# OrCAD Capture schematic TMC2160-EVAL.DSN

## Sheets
1 04_MOTOR-DRIVER: size Custom
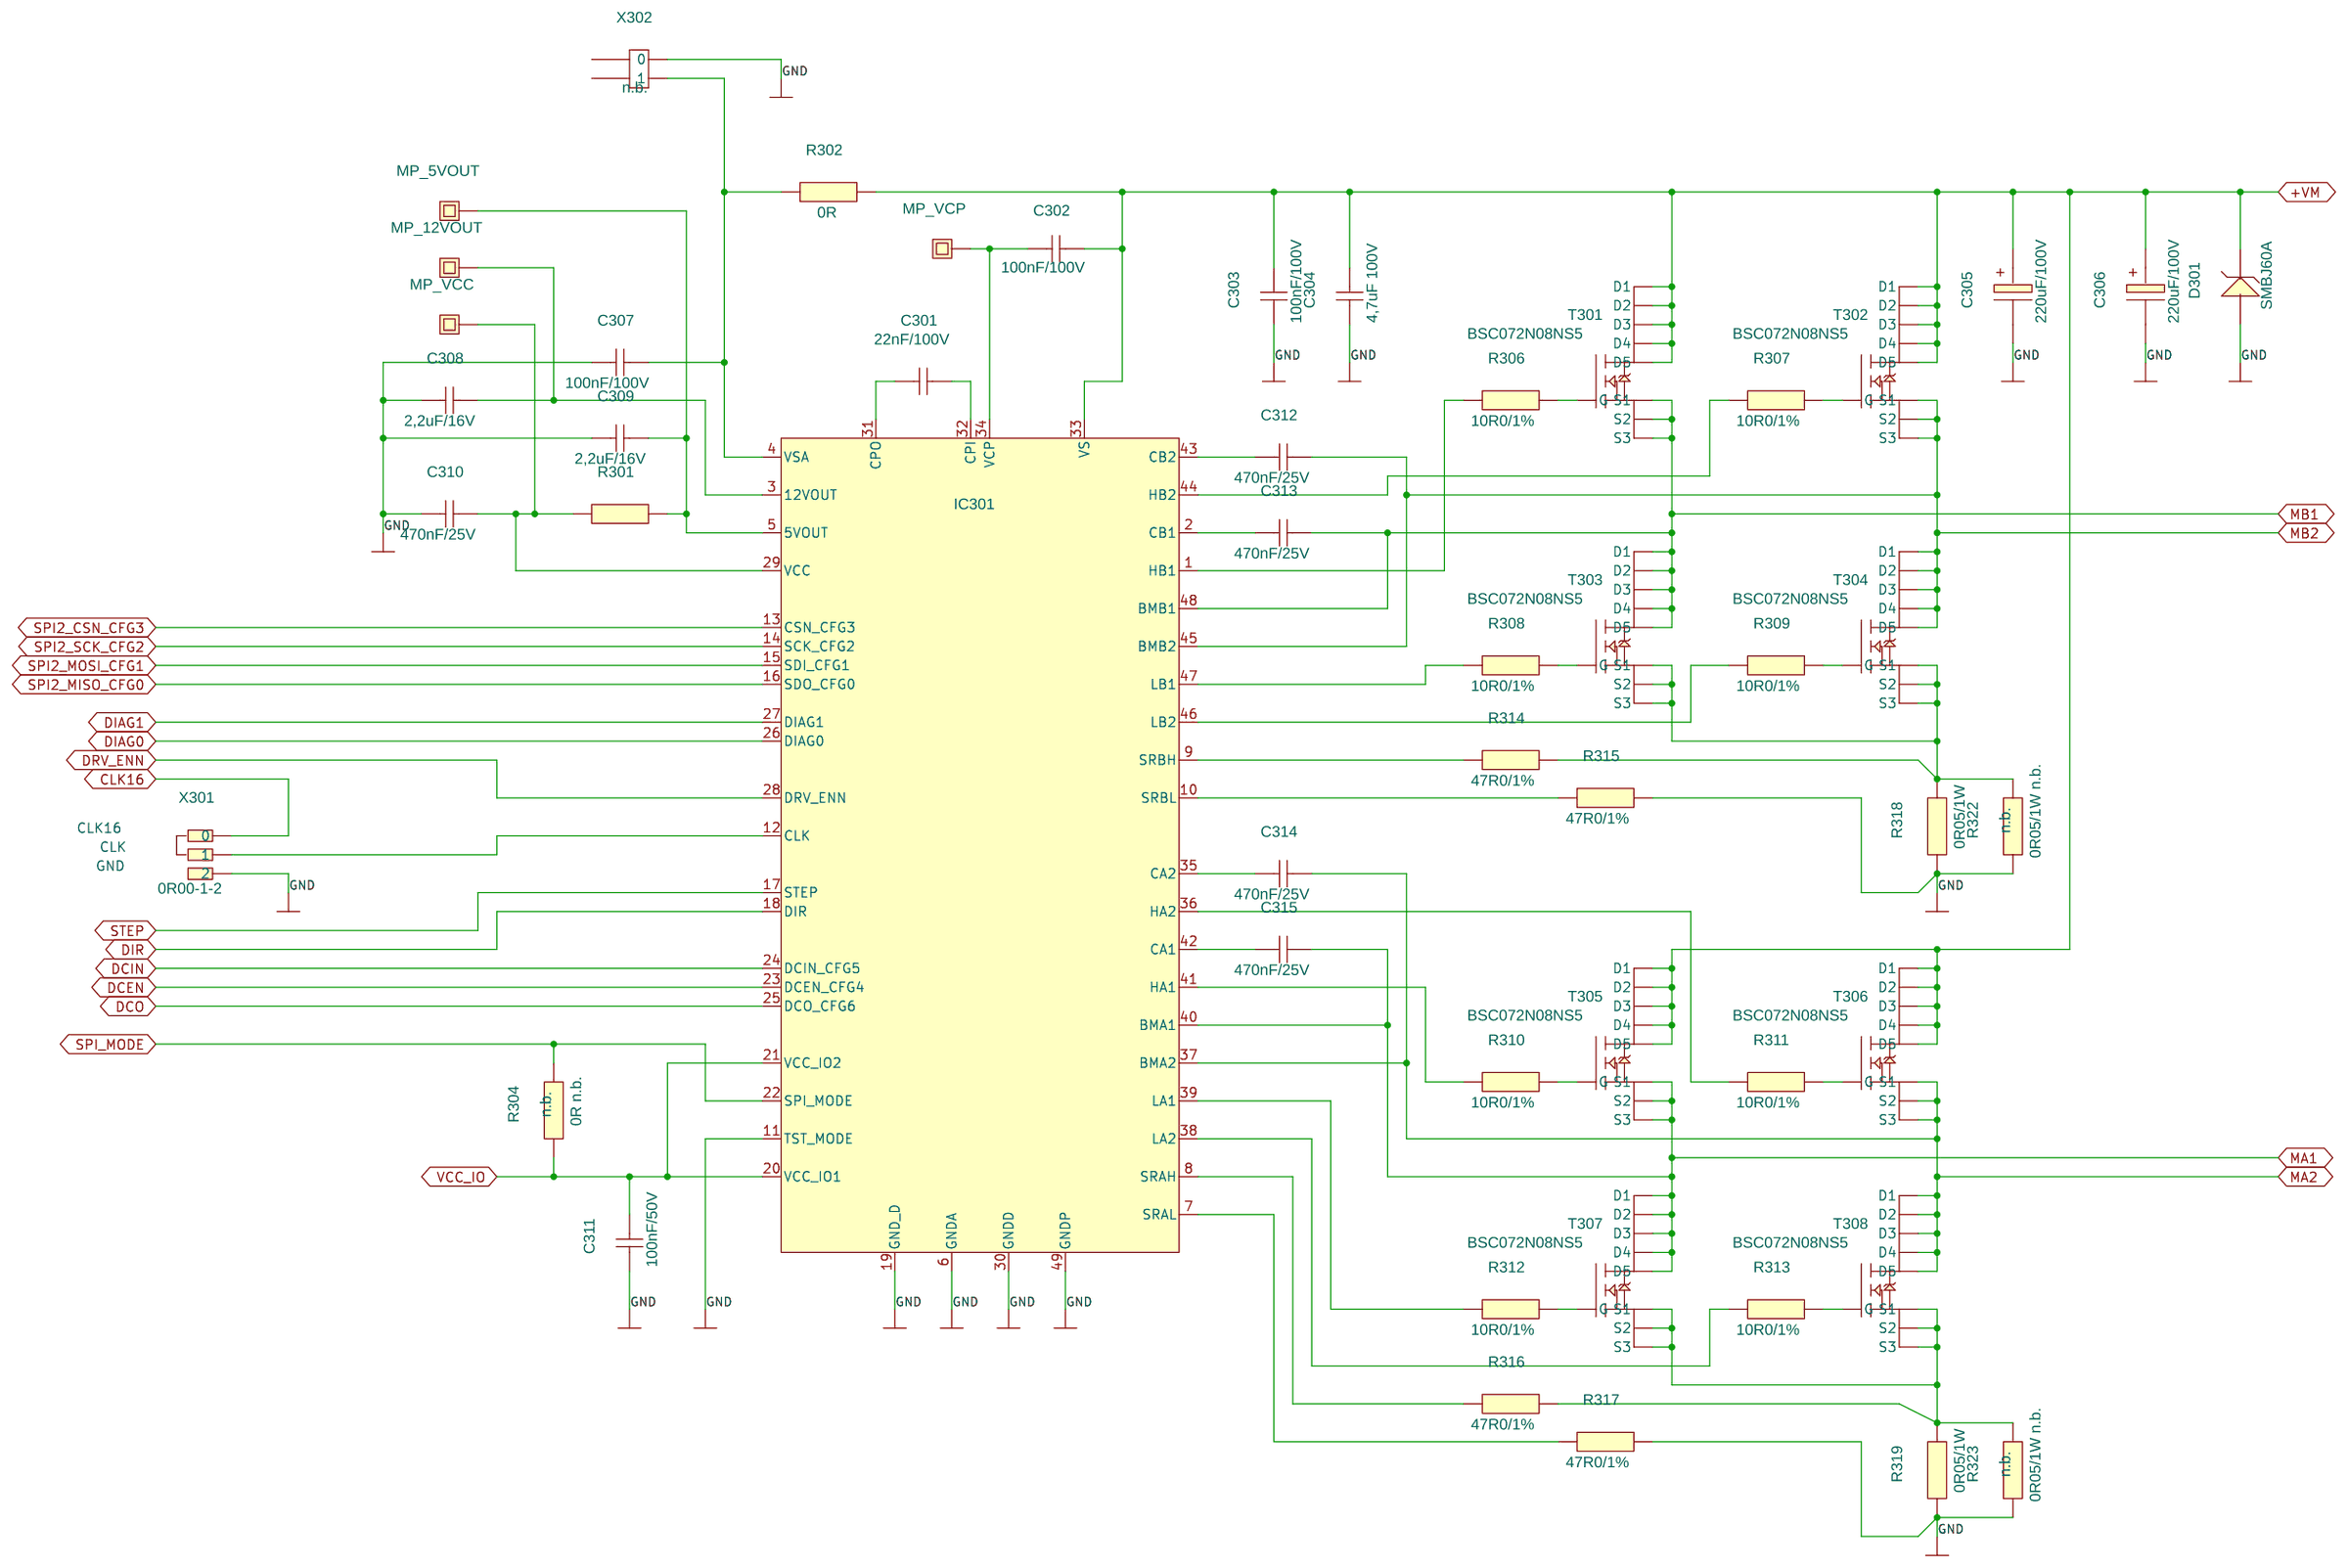
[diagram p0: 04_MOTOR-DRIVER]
2 03_MIXED-FUNCTIONS: size Custom
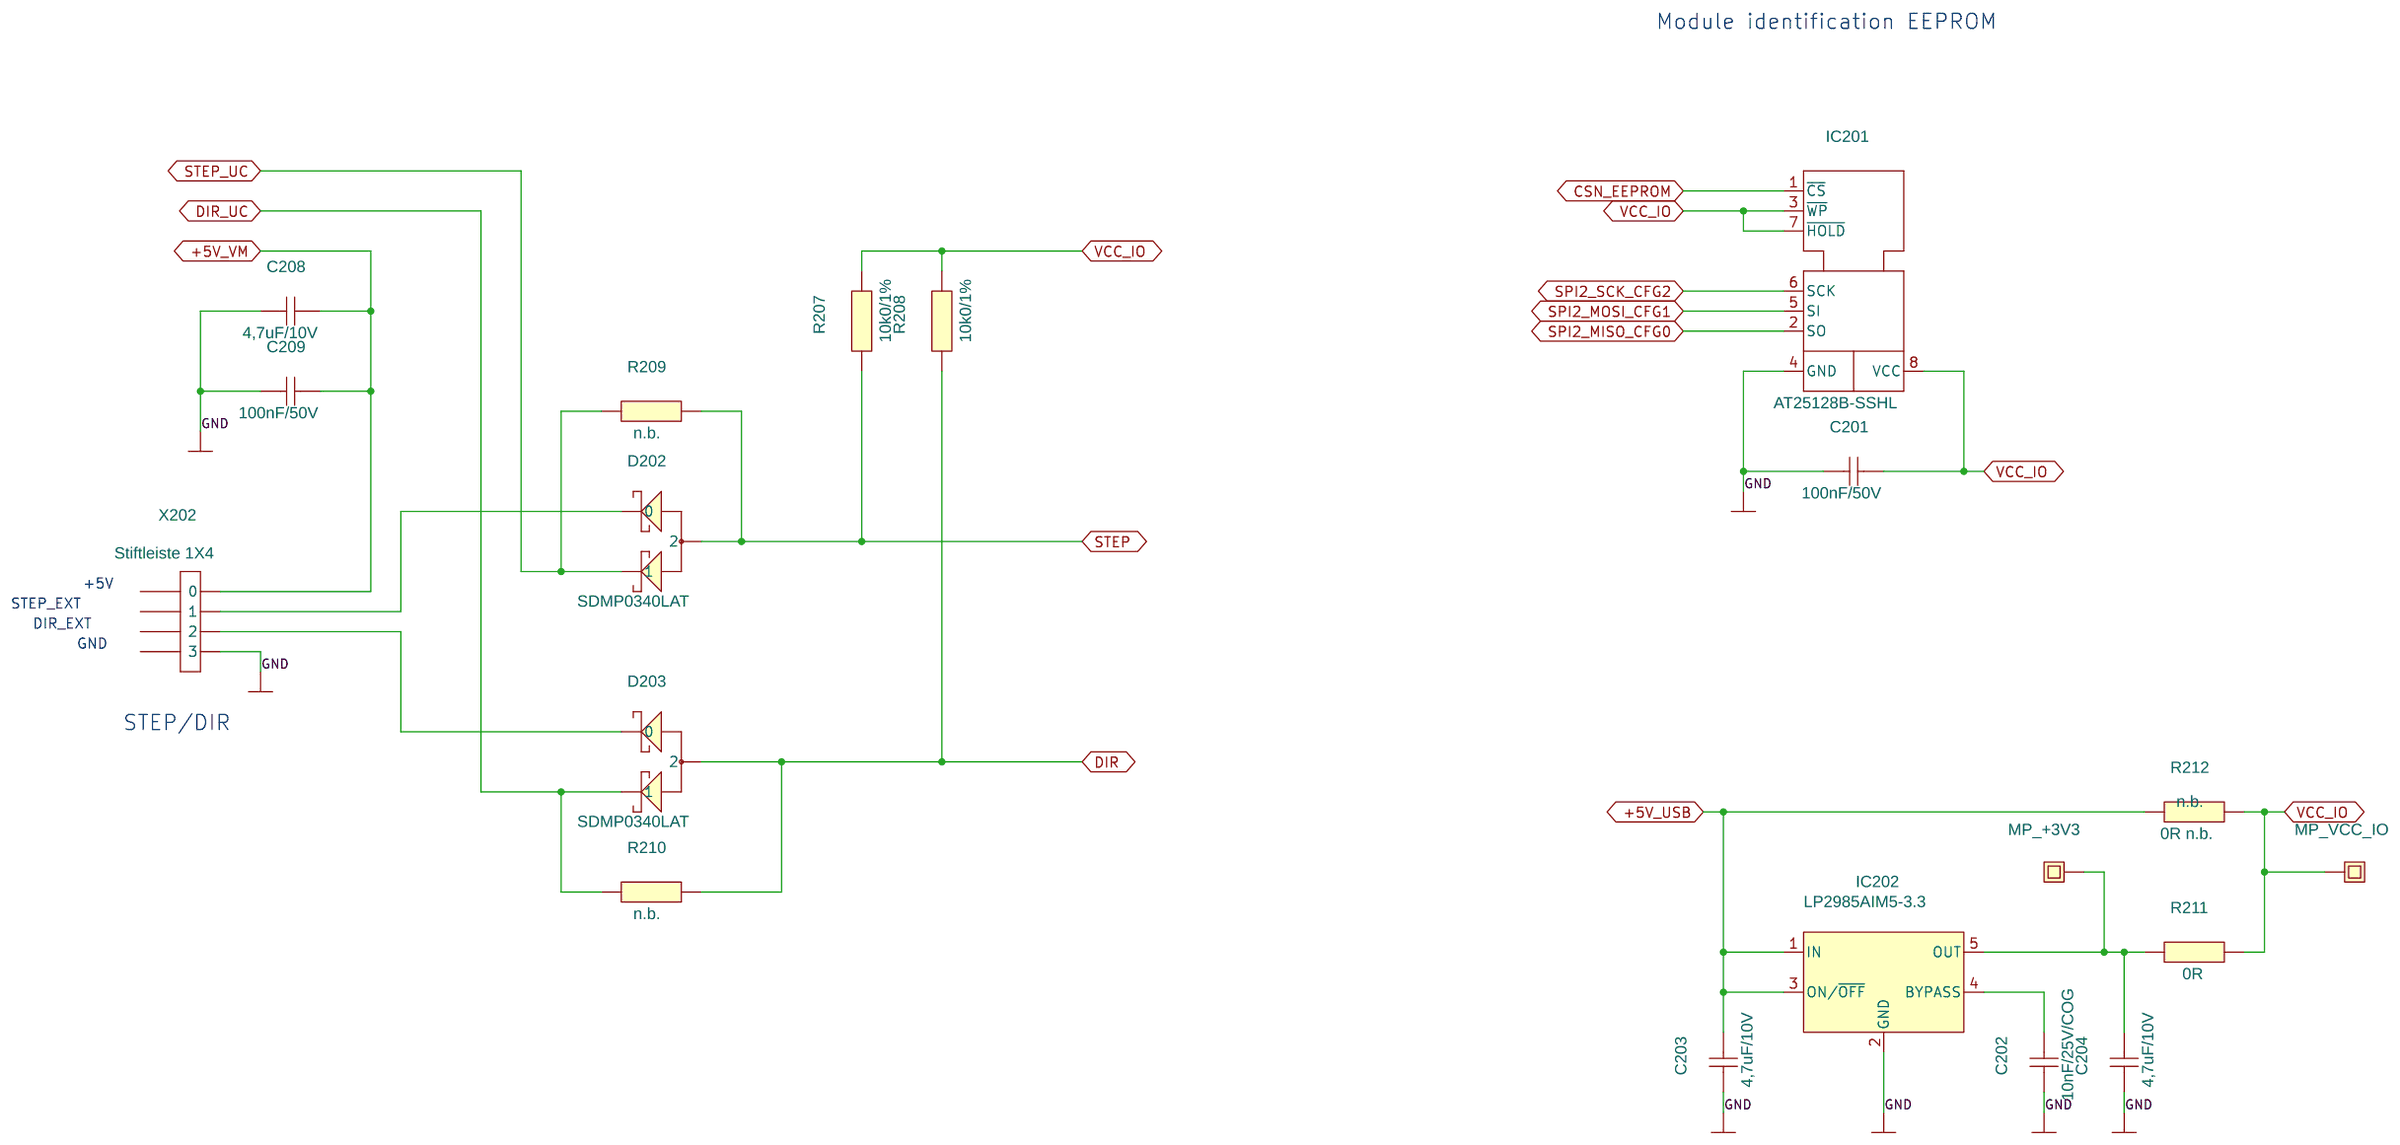
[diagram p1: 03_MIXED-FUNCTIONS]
3 02_CONNECTORS: size Custom
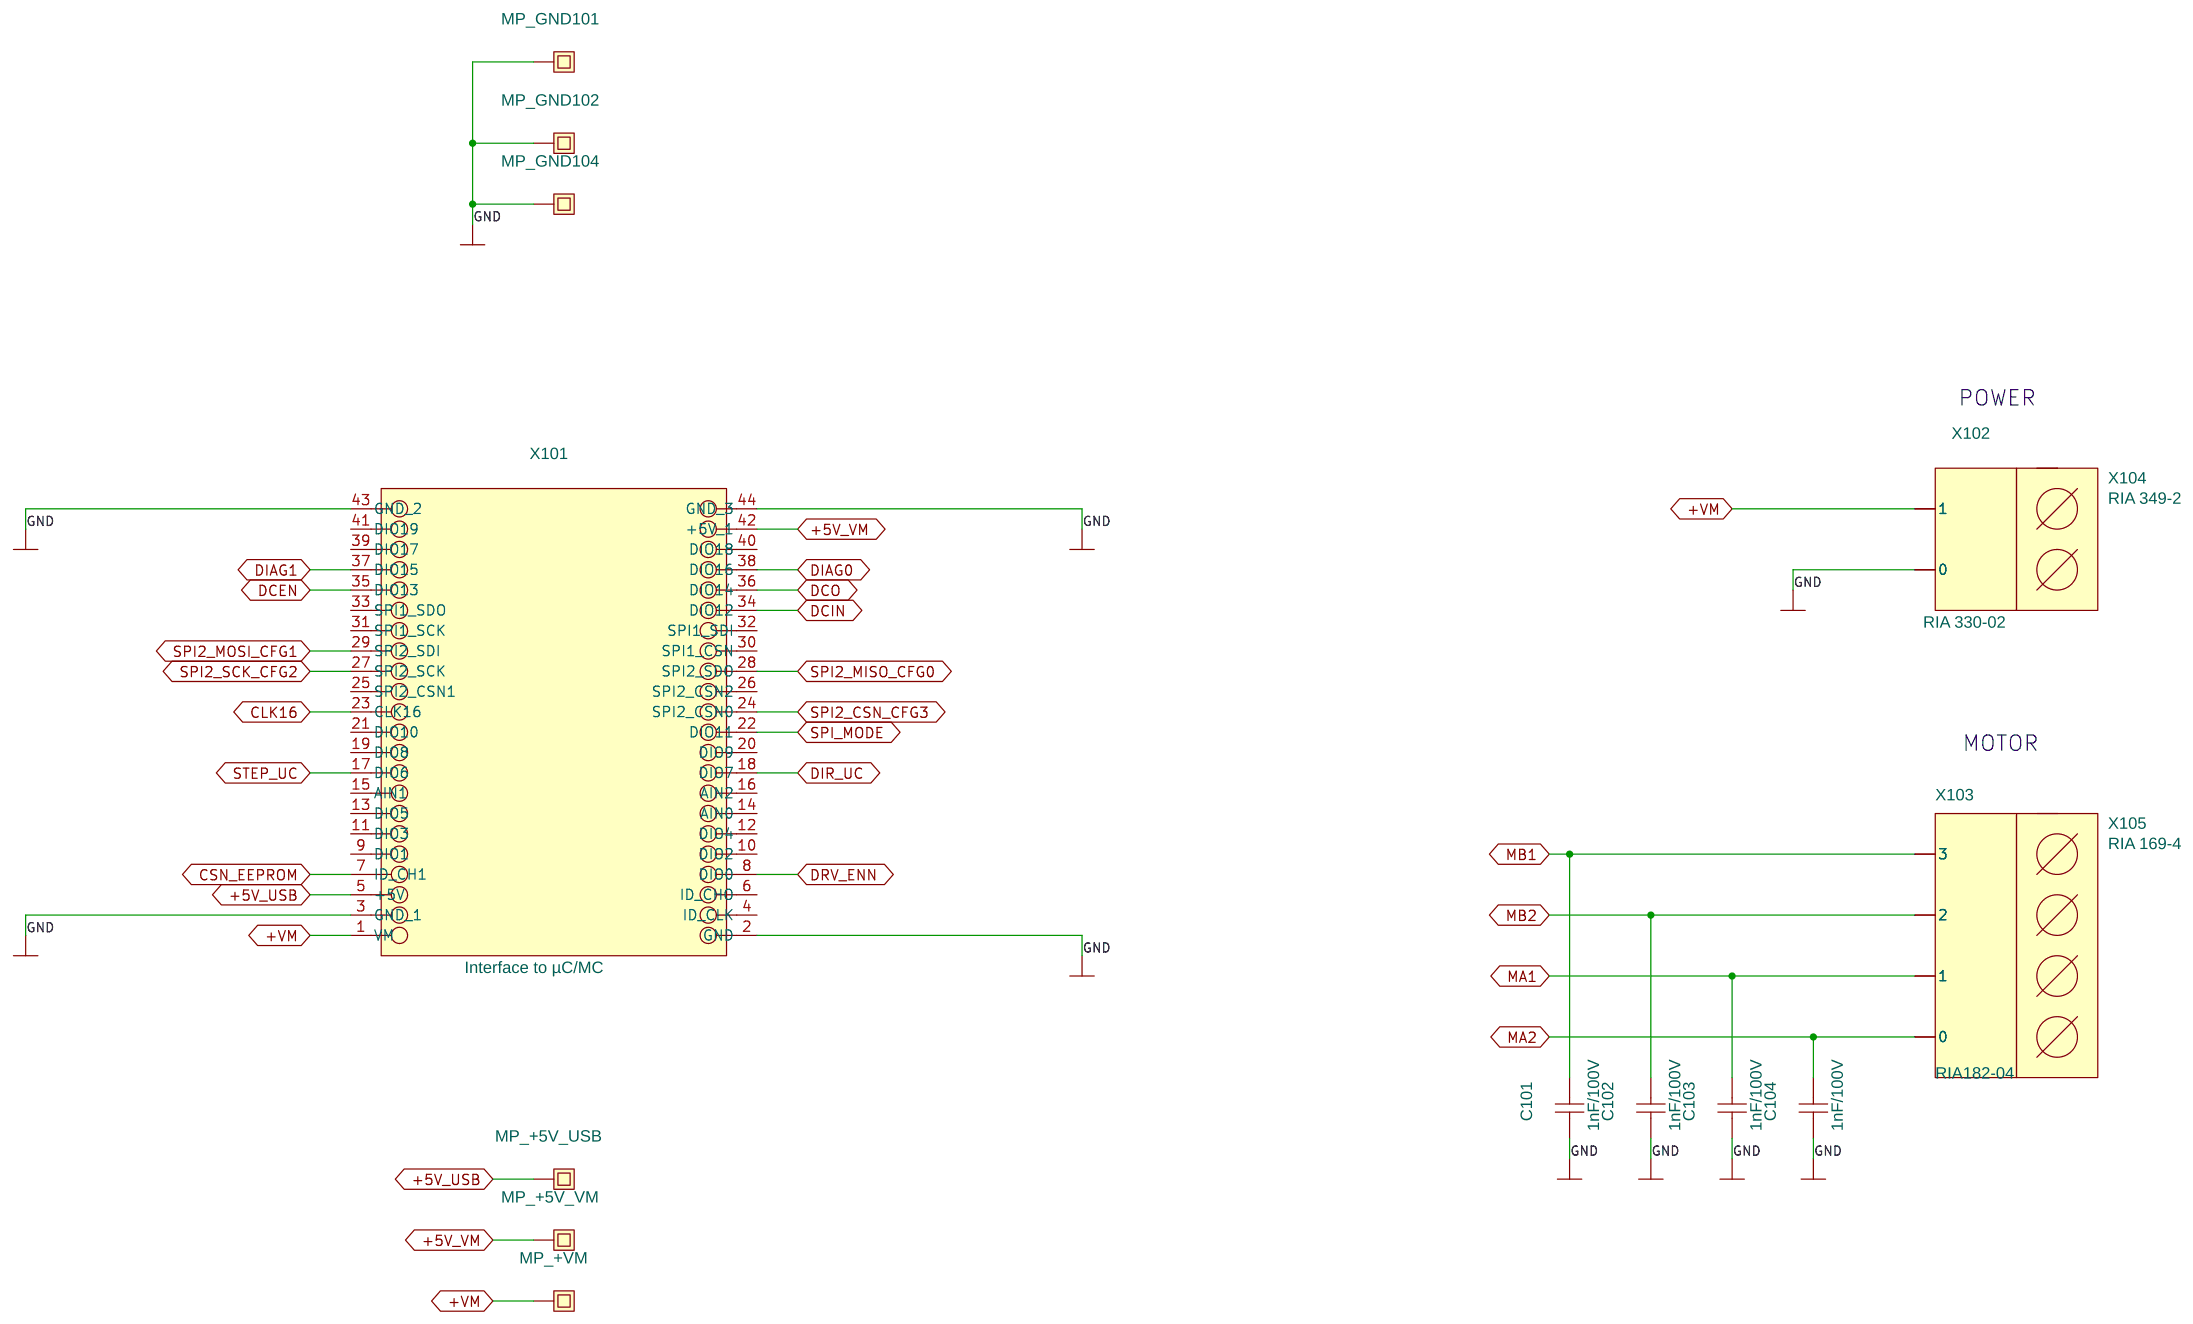
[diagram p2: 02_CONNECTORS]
4 01_PCB-PARTS: size Custom
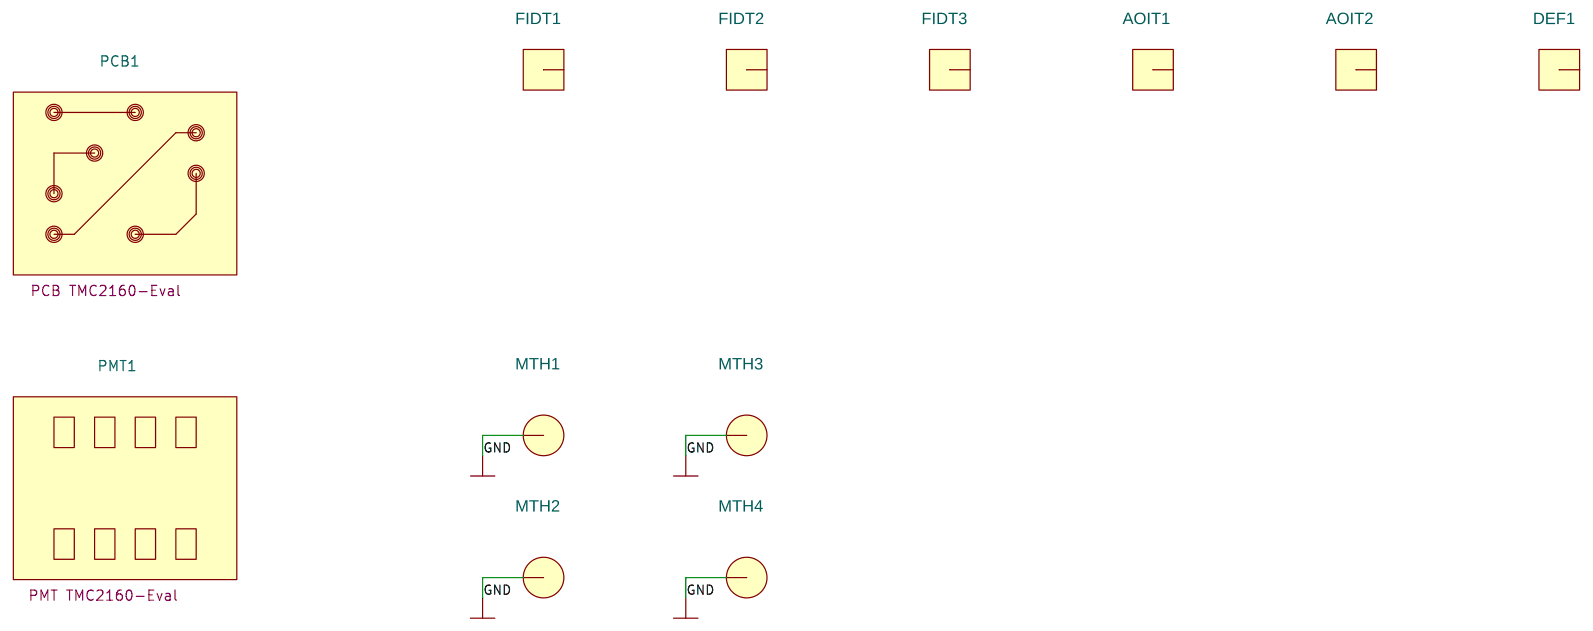
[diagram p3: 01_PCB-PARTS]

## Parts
sheet 01_PCB-PARTS
AOIT1  FID  [MARKER_KREUZ_AOI]
AOIT2  FID  [MARKER_KREUZ_AOI]
DEF1  FID  [MARKER_KREUZ_DEF]
FIDT1  FID  [FID1MMRUND]
FIDT2  FID  [FID1MMRUND]
FIDT3  FID  [FID1MMRUND]
MTH1  HOLE_NK  [MTHOLE3_2DK]
MTH2  HOLE_NK  [MTHOLE3_2DK]
MTH3  HOLE_NK  [MTHOLE3_2DK]
MTH4  HOLE_NK  [MTHOLE3_2DK]
PCB1  PCB  [PCBNULL]
PMT1  PMT  [PCBNULL]
sheet 02_CONNECTORS
C101  CAP-NP  [IEC-0603]
C102  CAP-NP  [IEC-0603]
C103  CAP-NP  [IEC-0603]
C104  CAP-NP  [IEC-0603]
MP_+5V_USB  TP  [TP_D1_0]
MP_+5V_VM  TP  [TP_D1_0]
MP_+VM  TP  [TP_D1_0]
MP_GND101  TP  [TP_D1_0]
MP_GND102  TP  [STILEI-1X1]
MP_GND104  TP  [STILEI-1X1]
X101  BULEI2X22_TRINAMIC  [SAMTEC_MPE_HLE-122-02-F-DV-A]
X102  KLEMME-1X2_STIFT  [RIA330_02_RM5]
X103  KLEMME-1X4_STIFT  [RIA182_04_RM35]
X104  KLEMME-1X2_SCHRAUB  [RIA349_02_RM5]
X105  KLEMME-1X4_SCHRAUB  [RIA169_04_RM35]
sheet 03_MIXED-FUNCTIONS
C201  CAP-NP  [IEC-0603]
C202  CAP-NP  [IEC-0603]
C203  CAP-NP  [IEC-0603]
C204  CAP-NP  [IEC-0603]
C208  CAP-NP  [IEC-0603]
C209  CAP-NP  [IEC-0603]
D202  DIODE-TVS-2-FACH  [SOT-523]
D203  DIODE-TVS-2-FACH  [SOT-523]
IC201  25128  [SO8_SOT96-1]
IC202  LP2985  [SOT23-5]
MP_+3V3  TP  [TP_D1_0]
MP_VCC_IO  TP  [TP_D1_0]
R207  RES  [IEC-0603]
R208  RES  [IEC-0603]
R209  RES  [IEC-0603]
R210  RES  [IEC-0603]
R211  RES  [IEC-0603]
R212  RES  [IEC-0603]
X202  JUMPER-1X4  [STILEI-1X4]
sheet 04_MOTOR-DRIVER
C301  CAP-NP  [IEC-0805]
C302  CAP-NP  [IEC-0805]
C303  CAP-NP  [IEC-0805]
C304  CAP-NP  [IEC-2220]
C305  CAP-POL  [ELKO-5_0_13X25]
C306  CAP-POL  [ELKO-5_0_13X25]
C307  CAP-NP  [IEC-0805]
C308  CAP-NP  [IEC-0603]
C309  CAP-NP  [IEC-0603]
C310  CAP-NP  [IEC-0603]
C311  CAP-NP  [IEC-0603]
C312  CAP-NP  [IEC-0603]
C313  CAP-NP  [IEC-0603]
C314  CAP-NP  [IEC-0603]
C315  CAP-NP  [IEC-0603]
D301  DIODE-TRANSIL-UNI  [DO-214AA_SMB_]
IC301  -  [TQFP48-EP]
MP_5VOUT  TP  [TP_D1_0]
MP_12VOUT  TP  [TP_D1_0]
MP_VCC  TP  [TP_D1_0]
MP_VCP  TP  [TP_D1_0]
R301  RES  [IEC-0603]
R302  RES  [IEC-0603]
R304  RES  [IEC-0603]
R306  RES  [IEC-0603]
R307  RES  [IEC-0603]
R308  RES  [IEC-0603]
R309  RES  [IEC-0603]
R310  RES  [IEC-0603]
R311  RES  [IEC-0603]
R312  RES  [IEC-0603]
R313  RES  [IEC-0603]
R314  RES  [IEC-0603]
R315  RES  [IEC-0603]
R316  RES  [IEC-0603]
R317  RES  [IEC-0603]
R318  RES  [IEC-2512]
R319  RES  [IEC-2512]
R322  RES  [IEC-2512]
R323  RES  [IEC-2512]
T301  BSC072N08N  [SO8-POWERFLAT_5X6]
T302  BSC072N08N  [SO8-POWERFLAT_5X6]
T303  BSC072N08N  [SO8-POWERFLAT_5X6]
T304  BSC072N08N  [SO8-POWERFLAT_5X6]
T305  BSC072N08N  [SO8-POWERFLAT_5X6]
T306  BSC072N08N  [SO8-POWERFLAT_5X6]
T307  BSC072N08N  [SO8-POWERFLAT_5X6]
T308  BSC072N08N  [SO8-POWERFLAT_5X6]
X301  JUMPER_R_1X3__12  [IEC-0603-JUMPER-1-2]
X302  Jumper  [JUMPER_1X2]

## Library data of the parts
AOIT1 AOIT2 = FID#1: BESCHREIBUNG: Fiducial; G&F-NR: 906-0006; Geometry.Height: 0.035mm; OPTION: n.b.
DEF1 = FID#2: BESCHREIBUNG: Defekt Marker; G&F-NR: 906-0006; Geometry.Height: 0.035mm; OPTION: n.b.
FIDT1-FIDT3 = FID: G&F-NR: 906-0006; OPTION: n.b.
MTH1-MTH4 = HOLE_NK: BESCHREIBUNG: Mounting Hole 3,2 mm DK; OPTION: n.b.; WERT: Mounting Hole 3,2 mm DK
PCB1 = PCB: BESCHREIBUNG: PCB TMC2160-Eval; OPTION: n.b.; WERT: PCB TMC2160-Eval
PMT1 = PMT: BESCHREIBUNG: Pastenmaske Top TMC2160-Eval; OPTION: n.b.; WERT: PMT TMC2160-Eval
C101-C104 = CAP-NP: BESCHREIBUNG: Multilayer Chip Capacitors, X7R, IEC-0603; BEST-NR #1: C0603C102K1RACTU; BEST-NR-LIEF: 1414606; Geometry.Height: 0.9mm; HERSTELLER #1: Kemet; LIEFERANT: Farnell; PREIS: 0,0235€ @ 100; WERT: 1nF/100V
MP_+5V_USB MP_+5V_VM MP_+VM MP_GND101 = TP#1: BESCHREIBUNG: TP on PCB
MP_GND102 MP_GND104 = TP: BESCHREIBUNG: Lötstützpunkt Zn Bohrung 1.0mm TYP 20-2137; BEST-NR #1: 20-2137; BEST-NR-LIEF: 8731128; G&F-NR: ???; HERSTELLER #1: VERO; LIEFERANT: Farnell; PREIS: 0,185@100; WERT: Lötstützpunkt 1mm
X101 = BULEI2X22_TRINAMIC: BESCHREIBUNG: BUCHSENLEISTE, SMD, RM 2,54mm, 2X22 Pol. Stehend, beidseitig steckbar; BEST-NR #1: MPE-098-3-044-1-NFX-YT; BEST-NR #2: HLE-122-02-F-DV-A; Geomertry.Height: 3.7mm; HERSTELLER #1: MPE-Garry; HERSTELLER #2: Samtec; WERT: Interface to µC/MC
X102 = KLEMME-1X2_STIFT: BESCHREIBUNG: Stiftleiste 2 Pol., RM 5mm, Einbaulage waagerecht, Steckkerstifte 1x1mm, geschlossene Wanne, kodierbar; BEST-NR #1: 31330102; HERSTELLER #1: RIA; WERT: RIA 330-02
X103 = KLEMME-1X4_STIFT: BESCHREIBUNG: Stiftleiste für Schraubklemme 90°, RIA 182, RM 3,5 mm, 4 Pol.; BEST-NR #1: 31182104; HERSTELLER #1: RIA; WERT: RIA182-04
X104 = KLEMME-1X2_SCHRAUB: BESCHREIBUNG: Schraubklemme steckbar, RIA 349, RM 5 mm, 2 Pol.; BEST-NR #1: 31349102; G&F-NR: 470-0535R; HERSTELLER #1: RIA; WERT: RIA 349-2
X105 = KLEMME-1X4_SCHRAUB: BESCHREIBUNG: Schraubklemme steckbar, RIA169, RM3,5 mm, 4 Pol.; BEST-NR #1: 31169104; G&F-NR: 470-0438R; HERSTELLER #1: RIA; WERT: RIA 169-4
C201 C209 C311 = CAP-NP#1: BESCHREIBUNG: Multilayer Chip Capacitors, X7R, 10%,  IEC-0603; BEST-NR-LIEF: 1288255; Geomertry.Height: 0.9mm; LIEFERANT: Farnell; PREIS: 0,013€ @ 100; WERT: 100nF/50V
C202 = CAP-NP#2: BESCHREIBUNG: Multilayer Chip Capacitors, COG, IEC-0603; BEST-NR #1: KEMET; BEST-NR-LIEF: 1457729; HERSTELLER #1: C0603C103J3GACTU; LIEFERANT: Farnell; PREIS: 0,158€ @ 100; WERT: 10nF/25V/COG
C203 C204 C208 = CAP-NP#3: BESCHREIBUNG: Multilayer Chip Capacitors, X5R, +-10%, IEC-0603; BEST-NR #1: C0603C475K8PACTU; BEST-NR #2: 12065C475KAT2A; BEST-NR #3: C1206C475K5RACTU; BEST-NR-LIEF: 1735545; Geometry.Height: 0.9mm; HERSTELLER #1: Kemet; HERSTELLER #2: AVX; HERSTELLER #3: Kemet; LIEFERANT: Farnell; PREIS: 0,237€ @ 100; WERT: 4,7uF/10V
D202 D203 = DIODE-TVS-2-FACH: BESCHREIBUNG: Dual Schottky Diodes SOT-523; BEST-NR #1: SDMP0340LAT; BEST-NR-LIEF: SDMP0340LAT-FDICT-ND; Geometry.Height: 0.9mm; HERSTELLER #1: Diodes Incorporated; LIEFERANT: Digi-Key; PREIS: 0,1742€ @ 100; WERT: SDMP0340LAT
IC201 = 25128: BESCHREIBUNG: SPI Serial EEPROM 128K, SO8; BEST-NR #1: AT25128B-SSHL-x; BEST-NR-LIEF: 1841575; Geometry.Height: 1.75mm; HERSTELLER #1: Atmel; LIEFERANT: Farnell; PREIS: 0,66€ @100; WERT: AT25128B-SSHL
IC202 = LP2985: BESCHREIBUNG: Micropower 150 mA Low-Noise Ultra Low-Dropout Regulator in SOT-23 Packages; BEST-NR #1: LP2985AIM5-3.3/NOPB; BEST-NR-LIEF: LP2985AIM5-3.3/NOPBCT-ND; Geometry.Height: 1.45mm; HERSTELLER #1: Texas Instruments; LIEFERANT: Digi-key; PREIS: 0,5364€ @100; WERT: LP2985AIM5-3.3
MP_5VOUT MP_12VOUT MP_+3V3 MP_VCC MP_VCC_IO MP_VCP = TP#2: BESCHREIBUNG: TP on PCB
R207 R208 = RES: BESCHREIBUNG: SMD-Resistor, 0603, 0,063W, 1%, 100ppm; BEST-NR-LIEF: 26E816; G&F-NR: 101-0006R; LIEFERANT: Bürklin; PREIS: 0,06; WERT: 10k0/1%
R209 R210 = RES#1: BESCHREIBUNG: SMD-Resistor, 0603, 0,063W, 1%; G&F-NR: 906-0002; OPTION: n.b.; WERT: n.b.
R211 = RES#2: BESCHREIBUNG: SMD-Resistor, IEC-0603, 0,063W, 5%; BEST-NR-LIEF: 1469739; G&F-NR: 100-0065R; Geometry.Height: 0.5mm; LIEFERANT: Farnell; PREIS: 0,026; WERT: 0R
R212 = RES#2: BESCHREIBUNG: SMD-Resistor, IEC-0603, 0,063W, 5%; BEST-NR-LIEF: 1469739; G&F-NR: 100-0065R; Geometry.Height: 0.5mm; LIEFERANT: Farnell; OPTION: n.b.; PREIS: 0,026; WERT: 0R n.b.
X202 = JUMPER-1X4: BESCHREIBUNG: STIFTLEISTE, RM2,54mm, 1X4 Pol.; BEST-NR #1: STL1-1260GGT-004U; HERSTELLER #1: Garry; Hoehe: 9.3mm; WERT: Stiftleiste 1X4
C301 = CAP-NP#4: BESCHREIBUNG: Multilayer Chip Capacitors, X7R, IEC-0805; BEST-NR-LIEF: 1414043; LIEFERANT: Farnell; PREIS: 0,052€ @100; WERT: 22nF/100V
C302 C303 C307 = CAP-NP#5: BESCHREIBUNG: Multilayer Chip Capacitors, X7R, IEC-0805; BEST-NR #1: C0805C104K1RAC; BEST-NR-LIEF: 2070444; G&F-NR: 181-0027; HERSTELLER #1: KEMET; LIEFERANT: Farnell; PREIS: 0,096€ @ 100; WERT: 100nF/100V
C304 = CAP-NP#6: BESCHREIBUNG: Multilayer Chip Capacitors, X7R, IEC-2220; BEST-NR #1: GRM55ER72A475KA01L; BEST-NR #2: C5750X7R2A475M; BEST-NR-LIEF: 490-1934-2-ND; G&F-NR: 183-0012R; HERSTELLER #1: MURATA; HERSTELLER #2: TDK; LIEFERANT: DigiKey; WERT: 4,7uF 100V
C305 C306 = CAP-POL: BESCHREIBUNG: Elko THT -55°C..105°C; High Ripple; RUBYCON ZLJ; D=12,5mm H=25mm; BEST-NR #1: 100ZLJ220M12.5X25; BEST-NR-LIEF: 2102459; Geometry.Height: 25.0mm; HERSTELLER #1: RUBYCON; LIEFERANT: Farnell; PREIS: 0,654€ @100; WERT: 220uF/100V
C308 C309 = CAP-NP#7: BESCHREIBUNG: Multilayer Chip Capacitors, X5R, IEC-0603; BEST-NR #1: C0603C225K4PACTU; BEST-NR-LIEF: 1288203; Geometry.Height: 0.9mm; HERSTELLER #1: KEMET; LIEFERANT: Farnell; PREIS: 0,0594€ @ 100; WERT: 2,2uF/16V
C310 C312-C315 = CAP-NP#8: BESCHREIBUNG: Multilayer Chip Capacitors, X7R, +-10%, IEC-0603; BEST-NR #1: C0603C474K3RACTU; BEST-NR #2: 06033C474KAT2A; BEST-NR #3: 885012206075; BEST-NR-LIEF: 2473546; Geometry.Height: 0.80mm; HERSTELLER #1: Kemet; HERSTELLER #2: AVX; HERSTELLER #3: Würth Elektronik; LIEFERANT: Farnell; PREIS: 0,0,0717€ @ 100; WERT: 470nF/25V
D301 = DIODE-TRANSIL-UNI: BESCHREIBUNG: Surface Mount TRANSZORB Transient Voltage Suppressors 600W; BEST-NR #1: SMBJ60A; BEST-NR #2: SMBJ60A; BEST-NR #3: SMBJ60A-E3/52; HERSTELLER #1: Littelfuse Inc; HERSTELLER #2: Fairchild/ON Semiconductor; HERSTELLER #3: Vishay Semiconductor; WERT: SMBJ60A
IC301 = TMC2160: BESCHREIBUNG: Universal high voltage controller for two-phase bipolar stepper motor. TQFP48-EP; BEST-NR #1: TMC2160-TA; HERSTELLER #1: TRINAMIC; HOEHE: 1.2mm; LIEFERANT: TRINAMIC; WERT: TMC2160-TA
R301 = RES#3: BESCHREIBUNG: SMD-Resistor, IEC-0603, 0,063W, 1%; LIEFERANT: Farnell; PREIS: 0,026; WERT: 2R20 1%
R302 = RES#7: BESCHREIBUNG: SMD-Resistor, IEC-0603, 0,063W, 5%; BEST-NR-LIEF: 1469739; G&F-NR: 100-0065R; Geometry.Height: 0.5mm; LIEFERANT: Farnell; PREIS: 0,026; WERT: 0R
R304 = RES#7: BESCHREIBUNG: SMD-Resistor, IEC-0603, 0,063W, 5%; BEST-NR-LIEF: 1469739; G&F-NR: 100-0065R; Geometry.Height: 0.5mm; LIEFERANT: Farnell; OPTION: n.b.; PREIS: 0,026; WERT: 0R n.b.
R306-R313 = RES#4: BESCHREIBUNG: SMD-Resistor, 0603, 0,063W, 1%, 100ppm; BEST-NR-LIEF: 2078895; G&F-NR: 101-0003R; Geometry.Height: 0.5mm; LIEFERANT: Farnell; PREIS: 0,012€ @ 100; TYPE: SMD-R0603; WERT: 10R0/1%
R314-R317 = RES#5: BESCHREIBUNG: SMD-Resistor, IEC-0603, 0,063W, 1%; G&F-NR: 100-0019; Geometry.Height: 0.55mm; WERT: 47R0/1%
R318 R319 = RES#6: BESCHREIBUNG: SMD-Resistor, 2512, 1 W, 1 %, 100ppm; BEST-NR #1: ERJL1WKF50MU; BEST-NR-LIEF: 1577586; HERSTELLER #1: PANASONIC; LIEFERANT: Farnell; PREIS: 0,875 @ 100; WERT: 0R05/1W
R322 R323 = RES#6: BESCHREIBUNG: SMD-Resistor, 2512, 1 W, 1 %, 100ppm; BEST-NR #1: ERJL1WKF50MU; BEST-NR-LIEF: 1577586; HERSTELLER #1: PANASONIC; LIEFERANT: Farnell; OPTION: n.b.; PREIS: 0,875 @ 100; WERT: 0R05/1W n.b.
T301-T308 = BSC072N08N: BESCHREIBUNG: OptiMOSTM5 Power-Transistor, 80V, 7,2mOhm, ID74A; BEST-NR #1: BSC072N08NS5ATMA1; BEST-NR-LIEF: 2725812; Geometry.Height: 1.1mm; HERSTELLER #1: Infineon; LIEFERANT: Farnell; PREIS: 0,874€ @ 100; WERT: BSC072N08NS5
X301 = JUMPER_R_1X3__12: BESCHREIBUNG: SMD-Jumper, 0603, default Pin 1 und 2 verbunden; Geometry.Height: 0.5mm; WERT: 0R00-1-2
X302 = JUMPER_1X2_OPEN: Stiftleiste, 2 Pol., Stehend, RM 2,54mm Länge 7mm incl. Jumper; OPTION: n.b.

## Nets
+5V_USB: C203.2(1) IC202.1(IN) IC202.3(ON/~{OFF}) MP_+5V_USB.1(0) R212.1(0) X101.5(+5V)
+5V_VM: C208.2(1) C209.2(1) MP_+5V_VM.1(0) X101.42(+5V_1) X202.1(0)
GND: C101.1(0) C102.1(0) C103.1(0) C104.1(0) C201.1(0) C202.1(0) C203.1(0) C204.1(0) C208.1(0) C209.1(0) C303.1(0) C304.1(0) C305.2(1) C306.2(1) C307.1(0) C308.1(0) C309.1(0) C310.1(0) C311.1(0) D301.2(AN) IC201.4(GND) IC202.2(GND) IC301.6(GNDA) IC301.11(TST_MODE) IC301.19(GND_D) IC301.30(GNDD) IC301.49(GNDP) MP_GND101.1(0) MP_GND102.1(0) MP_GND104.1(0) MTH1.1(0) MTH2.1(0) MTH3.1(0) MTH4.1(0) R315.2(1) R317.2(1) R318.1(0) R319.1(0) R322.1(0) R323.1(0) X101.2(GND) X101.3(GND_1) X101.43(GND_2) X101.44(GND_3) X102.1(0) X202.4(3) X301.3(2) X302.1(0)
VCC_IO: C201.2(1) C311.2(1) IC201.3(~{WP}) IC201.7(~{HOLD}) IC201.8(VCC) IC301.20(VCC_IO1) IC301.21(VCC_IO2) MP_VCC_IO.1(0) R207.2(1) R208.2(1) R211.2(1) R212.2(1) R304.1(0)
+VM: C302.2(1) C303.2(1) C304.2(1) C305.1(0) C306.1(0) D301.1(CA) IC301.33(VS) MP_+VM.1(0) R302.2(1) T301.5(D1) T301.6(D2) T301.7(D3) T301.8(D4) T301.9(D5) T302.5(D1) T302.6(D2) T302.7(D3) T302.8(D4) T302.9(D5) T305.5(D1) T305.6(D2) T305.7(D3) T305.8(D4) T305.9(D5) T306.5(D1) T306.6(D2) T306.7(D3) T306.8(D4) T306.9(D5) X101.1(VM) X102.2(1)
CLK16: X101.23(CLK16) X301.1(0)
CSN_EEPROM: IC201.1(~{CS}) X101.7(ID_CH1)
DCEN: IC301.23(DCEN_CFG4) X101.35(DIO13)
DCIN: IC301.24(DCIN_CFG5) X101.34(DIO12)
DCO: IC301.25(DCO_CFG6) X101.36(DIO14)
DIAG0: IC301.26(DIAG0) X101.38(DIO16)
DIAG1: IC301.27(DIAG1) X101.37(DIO15)
DIR: D203.3(2) IC301.18(DIR) R208.1(0) R210.2(1)
DIR_UC: D203.2(1) R210.1(0) X101.18(DIO7)
DRV_ENN: IC301.28(DRV_ENN) X101.8(DIO0)
MA1: C103.2(1) C315.2(1) IC301.40(BMA1) T305.1(S1) T305.2(S2) T305.3(S3) T307.5(D1) T307.6(D2) T307.7(D3) T307.8(D4) T307.9(D5) X103.2(1)
MA2: C104.2(1) C314.2(1) IC301.37(BMA2) T306.1(S1) T306.2(S2) T306.3(S3) T308.5(D1) T308.6(D2) T308.7(D3) T308.8(D4) T308.9(D5) X103.1(0)
MB1: C101.2(1) C313.2(1) IC301.48(BMB1) T301.1(S1) T301.2(S2) T301.3(S3) T303.5(D1) T303.6(D2) T303.7(D3) T303.8(D4) T303.9(D5) X103.4(3)
MB2: C102.2(1) C312.2(1) IC301.45(BMB2) T302.1(S1) T302.2(S2) T302.3(S3) T304.5(D1) T304.6(D2) T304.7(D3) T304.8(D4) T304.9(D5) X103.3(2)
SPI2_CSN_CFG3: IC301.13(CSN_CFG3) X101.24(SPI2_CSN0)
SPI2_MISO_CFG0: IC201.2(SO) IC301.16(SDO_CFG0) X101.28(SPI2_SDO)
SPI2_MOSI_CFG1: IC201.5(SI) IC301.15(SDI_CFG1) X101.29(SPI2_SDI)
SPI2_SCK_CFG2: IC201.6(SCK) IC301.14(SCK_CFG2) X101.27(SPI2_SCK)
SPI_MODE: IC301.22(SPI_MODE) R304.2(1) X101.22(DIO11)
STEP: D202.3(2) IC301.17(STEP) R207.1(0) R209.2(1)
STEP_UC: D202.2(1) R209.1(0) X101.17(DIO6)
N00503: C202.2(1) IC202.4(BYPASS)
N00509: C204.2(1) IC202.5(OUT) MP_+3V3.1(0) R211.1(0)
N00523: D202.1(0) X202.2(1)
N00549: D203.1(0) X202.3(2)
N00927: C301.1(0) IC301.31(CPO)
N00933: C301.2(1) IC301.32(CPI)
N00939: C302.1(0) IC301.34(VCP) MP_VCP.1(0)
N01079: C310.2(1) IC301.29(VCC) MP_VCC.1(0) R301.1(0)
N01201: C307.2(1) IC301.4(VSA) R302.1(0) X302.2(1)
N01219: C308.2(1) IC301.3(12VOUT) MP_12VOUT.1(0)
N01233: C309.2(1) IC301.5(5VOUT) MP_5VOUT.1(0) R301.2(1)
N01257: IC301.12(CLK) X301.2(1)
N01307: R306.2(1) T301.4(G)
N01309: R308.2(1) T303.4(G)
N01311: R309.2(1) T304.4(G)
N01313: R307.2(1) T302.4(G)
N01315: IC301.44(HB2) R307.1(0)
N01327: IC301.1(HB1) R306.1(0)
N01335: IC301.47(LB1) R308.1(0)
N01343: IC301.46(LB2) R309.1(0)
N01493: IC301.9(SRBH) R314.1(0)
N01497: C312.1(0) IC301.43(CB2)
N01501: C313.1(0) IC301.2(CB1)
N01505: R310.2(1) T305.4(G)
N01507: R312.2(1) T307.4(G)
N01509: R313.2(1) T308.4(G)
N01511: R311.2(1) T306.4(G)
N01513: IC301.41(HA1) R310.1(0)
N01521: IC301.39(LA1) R312.1(0)
N01529: IC301.38(LA2) R313.1(0)
N01541: R316.2(1) R319.2(1) R323.2(1) T307.1(S1) T307.2(S2) T307.3(S3) T308.1(S1) T308.2(S2) T308.3(S3)
N01623: C314.1(0) IC301.35(CA2)
N01627: C315.1(0) IC301.42(CA1)
N01631: IC301.8(SRAH) R316.1(0)
N01639: R314.2(1) R318.2(1) R322.2(1) T303.1(S1) T303.2(S2) T303.3(S3) T304.1(S1) T304.2(S2) T304.3(S3)
N01693: IC301.10(SRBL) R315.1(0)
N01697: IC301.7(SRAL) R317.1(0)
N01713: IC301.36(HA2) R311.1(0)

Not connected (* = marked no-connect by the designer): AOIT1 1(0); AOIT2 1(0); DEF1 1(0); FIDT1 1(0); FIDT2 1(0); FIDT3 1(0); X101 4(ID_CLK) 6(ID_CHO) 9(DIO1) 10(DIO2) 11(DIO3) 12(DIO4) 13(DIO5) 14(AIN0) 15(AIN1) 16(AIN2) 19(DIO8) 20(DIO9) 21(DIO10) 25(SPI2_CSN1) 26(SPI2_CSN2) 30(SPI1_CSN) 31(SPI1_SCK) 32(SPI1_SDI) 33(SPI1_SDO) 39(DIO17) 40(DIO18) 41(DIO19); X104 1(0); X105 1(0)

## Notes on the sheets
sheet 1
- CLK16
- CLK
- GND
sheet 2
- Module identification EEPROM
- +5V
- STEP_EXT
- DIR_EXT
- GND
- STEP/DIR
sheet 3
- POWER
- MOTOR
